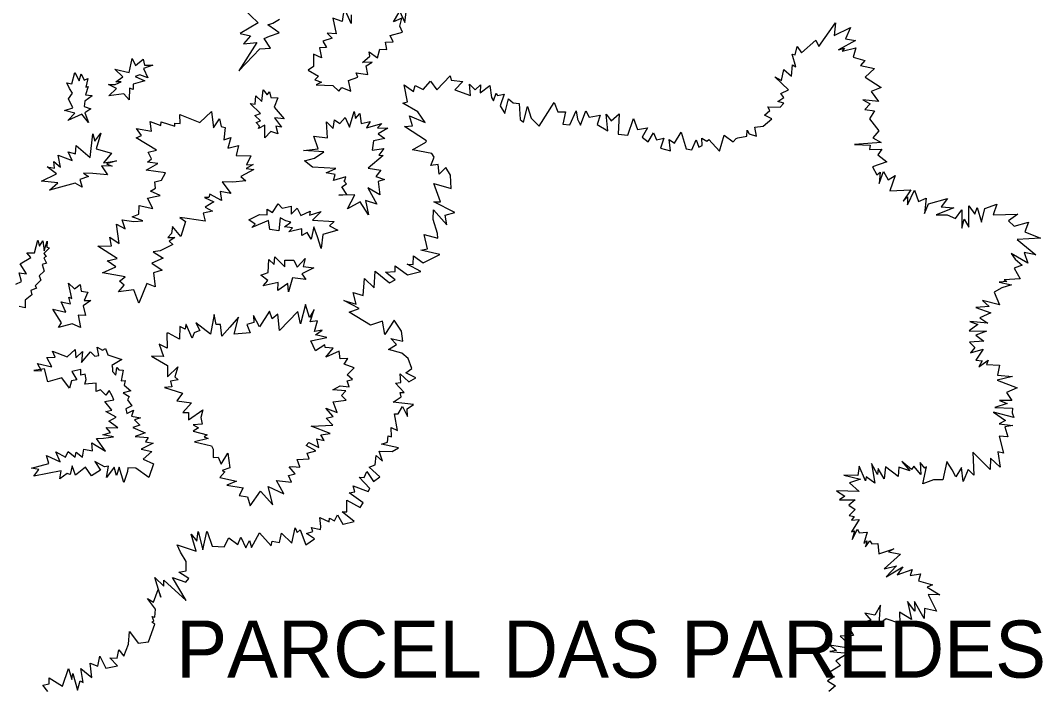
# Model space of a CAD drawing. Extents: x 662444 to 1640468, y 7452018 to 9606170.
# Drawn here: x 1134383 to 1146086, y 8020157 to 8027789 of the extents above; entities that cross this region are included whole.
import ezdxf

# ---------------------------------------------------------------- set-up
doc = ezdxf.new("R2010")
doc.units = 0
doc.layers.add('Level 1', color=7, linetype='Continuous')
doc.layers.add('Level 3', color=7, linetype='Continuous')

msp = doc.modelspace()

# ---------------------------------------------------------------- linework, layer by layer
at = {"layer": 'Level 1'}
for points in [[(1136928, 8027930), (1137105, 8027763), (1136898, 8027639), (1137018, 8027612), (1136938, 8027522), (1137089, 8027536), (1136882, 8027212), (1137125, 8027463), (1137246, 8027469), (1137173, 8027581), (1137235, 8027610), (1137346, 8027647), (1137304, 8027677), (1137217, 8027738), (1137271, 8027757), (1137349, 8027804)], [(1138170, 8027851), (1138169, 8027754), (1138090, 8027932), (1138065, 8027777), (1137958, 8027816), (1137996, 8027634), (1137896, 8027643), (1137951, 8027587), (1137845, 8027550), (1137886, 8027477), (1137805, 8027476), (1137831, 8027361), (1137740, 8027402), (1137738, 8027259), (1137676, 8027218), (1137796, 8027150), (1137753, 8027108), (1137829, 8027080), (1137768, 8027052), (1137959, 8027045), (1138029, 8026979), (1138061, 8027021), (1138167, 8026978), (1138138, 8027101), (1138246, 8027139), (1138225, 8027187), (1138360, 8027170), (1138340, 8027268), (1138410, 8027311), (1138298, 8027307), (1138383, 8027381), (1138376, 8027428), (1138471, 8027360), (1138497, 8027458), (1138579, 8027457), (1138561, 8027539), (1138651, 8027544), (1138617, 8027617), (1138757, 8027653), (1138726, 8027723), (1138749, 8027814), (1138653, 8027772), (1138715, 8027874)], [(1138724, 8027897), (1138784, 8027764), (1138804, 8027913)], [(1141809, 8026425), (1141872, 8026382), (1141947, 8026508), (1142007, 8026319), (1142071, 8026307), (1142118, 8026420), (1142152, 8026335), (1142187, 8026354), (1142186, 8026439), (1142243, 8026406), (1142264, 8026426), (1142388, 8026291), (1142440, 8026474), (1142543, 8026396), (1142577, 8026436), (1142598, 8026445), (1142700, 8026463), (1142703, 8026532), (1142727, 8026490), (1142810, 8026462), (1142793, 8026567), (1142886, 8026576), (1142986, 8026661), (1142903, 8026704), (1142962, 8026756), (1142942, 8026800), (1143080, 8026796), (1143125, 8026840), (1143054, 8026858), (1143124, 8026907), (1143090, 8026951), (1143176, 8026994), (1143020, 8027143), (1143097, 8027101), (1143125, 8027228), (1143212, 8027149), (1143222, 8027279), (1143261, 8027257), (1143220, 8027404), (1143253, 8027395), (1143276, 8027489), (1143325, 8027419), (1143492, 8027561), (1143524, 8027489), (1143716, 8027761), (1143701, 8027616), (1143886, 8027708), (1143830, 8027578), (1143945, 8027560), (1143748, 8027451), (1143818, 8027470), (1143790, 8027437), (1143950, 8027475), (1143917, 8027366), (1144050, 8027331), (1144002, 8027274), (1144162, 8027238), (1144054, 8027139), (1144237, 8027021), (1144122, 8026976), (1144206, 8026861), (1144027, 8026878), (1144112, 8026834), (1144051, 8026767), (1144161, 8026753), (1144105, 8026663), (1144213, 8026523), (1144141, 8026444), (1144239, 8026390), (1143931, 8026367), (1144113, 8026361), (1144104, 8026310), (1144247, 8026313), (1144199, 8026250), (1144304, 8026168), (1144140, 8026112), (1144188, 8026021), (1144228, 8026050), (1144214, 8025920), (1144264, 8026057), (1144318, 8025962), (1144398, 8026014), (1144336, 8025835), (1144579, 8025847), (1144489, 8025718), (1144541, 8025766), (1144539, 8025677), (1144621, 8025844), (1144664, 8025714), (1144753, 8025752), (1144733, 8025578), (1144782, 8025687), (1144996, 8025747), (1144927, 8025654), (1145069, 8025642), (1144867, 8025562), (1144995, 8025562), (1145091, 8025519), (1145161, 8025619), (1145162, 8025407), (1145188, 8025513)], [(1135899, 8027275), (1135793, 8027237), (1135841, 8027131), (1135749, 8027164), (1135697, 8027148), (1135806, 8027097), (1135672, 8027060), (1135674, 8026996), (1135632, 8027012), (1135628, 8026878), (1135568, 8026948), (1135396, 8026923), (1135483, 8027010), (1135390, 8027053), (1135469, 8027056), (1135534, 8027084), (1135476, 8027086), (1135554, 8027142), (1135464, 8027232), (1135627, 8027194), (1135663, 8027351), (1135701, 8027271), (1135786, 8027345), (1135804, 8027276), (1135899, 8027275)], [(1135163, 8026619), (1135084, 8026716), (1134924, 8026642), (1135006, 8026726), (1134886, 8026758), (1134982, 8026788), (1134934, 8026890), (1134977, 8026957), (1134946, 8027008), (1134915, 8027072), (1134971, 8027062), (1135006, 8027191), (1135054, 8027097), (1135077, 8027176), (1135113, 8027105), (1135154, 8027125), (1135131, 8027026), (1135159, 8027030), (1135128, 8026937), (1135197, 8026929), (1135204, 8026924), (1135118, 8026865), (1135111, 8026804), (1135189, 8026774), (1135119, 8026730), (1135163, 8026619)], [(1138587, 8022959), (1138594, 8023028), (1138632, 8023017), (1138628, 8023125), (1138701, 8023091), (1138666, 8023281), (1138707, 8023282), (1138757, 8023365), (1138814, 8023251), (1138811, 8023338), (1138882, 8023387), (1138651, 8023414), (1138742, 8023476), (1138731, 8023527), (1138777, 8023526), (1138678, 8023634), (1138737, 8023642), (1138732, 8023739), (1138830, 8023647), (1138910, 8023695), (1138797, 8023752), (1138866, 8023803), (1138822, 8023917), (1138748, 8023978), (1138598, 8024017), (1138690, 8024075), (1138623, 8024144), (1138763, 8024114), (1138746, 8024229), (1138661, 8024355), (1138555, 8024192), (1138527, 8024342), (1138390, 8024297), (1138146, 8024445), (1138261, 8024490), (1138085, 8024581), (1138228, 8024537), (1138194, 8024672), (1138308, 8024639), (1138323, 8024831), (1138432, 8024725), (1138445, 8024918), (1138610, 8024783), (1138673, 8024816), (1138561, 8024905), (1138673, 8024911), (1138675, 8024978), (1138816, 8024876), (1138967, 8024913), (1138809, 8024997), (1138878, 8024991), (1138882, 8025093), (1138994, 8025013), (1139184, 8025107), (1138968, 8025157), (1139043, 8025173), (1139004, 8025335), (1139162, 8025295), (1139158, 8025348), (1139107, 8025508), (1139114, 8025620), (1139266, 8025447), (1139244, 8025558), (1139358, 8025590), (1139117, 8025712), (1139193, 8025710), (1139115, 8025919), (1139313, 8025862), (1139308, 8026017), (1139252, 8026104), (1139178, 8026029), (1139164, 8026140), (1139081, 8026127), (1139120, 8026223), (1139093, 8026265), (1138871, 8026305), (1139026, 8026395), (1139032, 8026410), (1138781, 8026574), (1138871, 8026581), (1138836, 8026695), (1139015, 8026618), (1138932, 8026740), (1138762, 8026841), (1138813, 8026857), (1138778, 8027049), (1138883, 8026975), (1138904, 8027043), (1138994, 8026999), (1139077, 8027093), (1139151, 8026994), (1139304, 8027155), (1139313, 8027106), (1139450, 8027089), (1139357, 8026993), (1139537, 8026928), (1139524, 8027059), (1139588, 8026995), (1139651, 8027052), (1139648, 8026958), (1139759, 8027045)], [(1137180, 8026444), (1137181, 8026590), (1137107, 8026549), (1137120, 8026578), (1137080, 8026619), (1137130, 8026637), (1137066, 8026700), (1137130, 8026722), (1137013, 8026838), (1137070, 8026831), (1137077, 8026926), (1137147, 8026859), (1137161, 8026992), (1137208, 8026936), (1137235, 8026969), (1137251, 8026905), (1137328, 8026902), (1137286, 8026796), (1137401, 8026662), (1137290, 8026673), (1137372, 8026564), (1137305, 8026576), (1137329, 8026488), (1137248, 8026516), (1137180, 8026444)], [(1139759, 8027045), (1139777, 8026905), (1139799, 8026866), (1139829, 8026954), (1139845, 8026930), (1139922, 8026943), (1139876, 8026812), (1139928, 8026724), (1139971, 8026891), (1140023, 8026846), (1140092, 8026836), (1140106, 8026654), (1140144, 8026625), (1140188, 8026802), (1140230, 8026668), (1140321, 8026576), (1140494, 8026848), (1140537, 8026742), (1140624, 8026742), (1140594, 8026600), (1140675, 8026592), (1140744, 8026753), (1140762, 8026656), (1140795, 8026590), (1140855, 8026752), (1140893, 8026682), (1141020, 8026703), (1140987, 8026598), (1141109, 8026522), (1141091, 8026714), (1141145, 8026640), (1141238, 8026720), (1141227, 8026485), (1141339, 8026474), (1141404, 8026665), (1141449, 8026541), (1141562, 8026558), (1141500, 8026451), (1141569, 8026397), (1141632, 8026502), (1141665, 8026420), (1141748, 8026439), (1141713, 8026324), (1141825, 8026295), (1141809, 8026425)], [(1135737, 8024551), (1135680, 8024703), (1135505, 8024679), (1135570, 8024756), (1135515, 8024803), (1135582, 8024850), (1135324, 8024899), (1135474, 8024966), (1135374, 8025036), (1135492, 8025060), (1135269, 8025203), (1135425, 8025205), (1135408, 8025307), (1135513, 8025233), (1135482, 8025454), (1135580, 8025402), (1135548, 8025505), (1135680, 8025485), (1135783, 8025492), (1135661, 8025537), (1135738, 8025568), (1135742, 8025667), (1135897, 8025634), (1135839, 8025752), (1135925, 8025771), (1135984, 8025783), (1135870, 8025832), (1135928, 8025866), (1135920, 8025938), (1135999, 8025960), (1136044, 8026043), (1135822, 8026072), (1135957, 8026151), (1135837, 8026166), (1135884, 8026202), (1135846, 8026280), (1135939, 8026302), (1135706, 8026442), (1135768, 8026471), (1135711, 8026552), (1135882, 8026521), (1135867, 8026630), (1135992, 8026584), (1135995, 8026626), (1136150, 8026577), (1136151, 8026611), (1136213, 8026609), (1136208, 8026710), (1136435, 8026621), (1136572, 8026747), (1136595, 8026560), (1136662, 8026662), (1136680, 8026572), (1136727, 8026563), (1136713, 8026421), (1136793, 8026446), (1136756, 8026327), (1136880, 8026357), (1136854, 8026242), (1137020, 8026237), (1136970, 8026134), (1137046, 8026139), (1136966, 8026093), (1137055, 8026080), (1136907, 8026000), (1136962, 8025950), (1136815, 8025937), (1136693, 8025941), (1136791, 8025805), (1136671, 8025830), (1136684, 8025727), (1136553, 8025800), (1136541, 8025759), (1136490, 8025761), (1136596, 8025712), (1136499, 8025650), (1136582, 8025602), (1136473, 8025580), (1136496, 8025490), (1136290, 8025519), (1136206, 8025532), (1136271, 8025486), (1136219, 8025312), (1136123, 8025428), (1136113, 8025347), (1136071, 8025301), (1136150, 8025301), (1136087, 8025260), (1136129, 8025221), (1135981, 8025149), (1135902, 8025139), (1136017, 8025066), (1135887, 8025008), (1136005, 8024929), (1135907, 8024898), (1135925, 8024737), (1135828, 8024775), (1135737, 8024551)], [(1138369, 8025560), (1138271, 8025709), (1138128, 8025629), (1138210, 8025792), (1138029, 8025786), (1138121, 8025795), (1138063, 8025882), (1138117, 8025916), (1138085, 8025952), (1138098, 8025957), (1138107, 8025995), (1137968, 8025956), (1137987, 8026022), (1137885, 8026041), (1137993, 8026091), (1137727, 8026107), (1137637, 8026181), (1137750, 8026209), (1137855, 8026282), (1137625, 8026300), (1137792, 8026317), (1137741, 8026464), (1137898, 8026444), (1137887, 8026628), (1137964, 8026549), (1137978, 8026651), (1138040, 8026608), (1138099, 8026678), (1138149, 8026567), (1138203, 8026746), (1138218, 8026667), (1138269, 8026723), (1138283, 8026606), (1138388, 8026630), (1138345, 8026557), (1138521, 8026608), (1138470, 8026558), (1138588, 8026555), (1138479, 8026489), (1138556, 8026435), (1138427, 8026410), (1138411, 8026304), (1138543, 8026321), (1138486, 8026246), (1138537, 8026243), (1138366, 8026097), (1138511, 8026072), (1138452, 8025999), (1138551, 8025968), (1138479, 8025945), (1138497, 8025789), (1138359, 8025872), (1138462, 8025682), (1138334, 8025727), (1138369, 8025560)], [(1134623, 8025949), (1134794, 8026032), (1134689, 8026110), (1134774, 8026097), (1134765, 8026171), (1134840, 8026107), (1134813, 8026244), (1134974, 8026183), (1134930, 8026284), (1135014, 8026261), (1135020, 8026355), (1135181, 8026217), (1135210, 8026489), (1135233, 8026407), (1135303, 8026496), (1135251, 8026317), (1135426, 8026268), (1135333, 8026156), (1135482, 8026181), (1135369, 8026145), (1135434, 8026120), (1135312, 8026123), (1135380, 8026019), (1135212, 8026034), (1135104, 8026038), (1135160, 8026000), (1135064, 8025966), (1135091, 8025877), (1135011, 8025924), (1134840, 8025878), (1134716, 8025843), (1134809, 8025927), (1134623, 8025949)], [(1137845, 8025337), (1137827, 8025176), (1137785, 8025310), (1137743, 8025425), (1137711, 8025284), (1137666, 8025360), (1137604, 8025324), (1137604, 8025400), (1137457, 8025365), (1137496, 8025412), (1137407, 8025424), (1137478, 8025479), (1137422, 8025491), (1137357, 8025526), (1137340, 8025379), (1137240, 8025392), (1137223, 8025497), (1137032, 8025416), (1137071, 8025456), (1136996, 8025504), (1137118, 8025565), (1137207, 8025562), (1137209, 8025628), (1137268, 8025588), (1137335, 8025688), (1137379, 8025638), (1137482, 8025662), (1137481, 8025571), (1137553, 8025638), (1137594, 8025554), (1137700, 8025604), (1137691, 8025559), (1137825, 8025600), (1137727, 8025501), (1137973, 8025486), (1137920, 8025434), (1138016, 8025387), (1137845, 8025337)], [(1145188, 8025513), (1145241, 8025420), (1145242, 8025664), (1145310, 8025568), (1145338, 8025646), (1145387, 8025476), (1145425, 8025636), (1145562, 8025685), (1145520, 8025563), (1145805, 8025569), (1145697, 8025494), (1145761, 8025433), (1145926, 8025476), (1145882, 8025368), (1146061, 8025293), (1145794, 8025278), (1146011, 8025103), (1145875, 8025130), (1145917, 8025009), (1145728, 8025117), (1145774, 8025052), (1145854, 8024986), (1145763, 8024952), (1145831, 8024830), (1145647, 8024818), (1145676, 8024799), (1145590, 8024790), (1145729, 8024759), (1145621, 8024724), (1145532, 8024676), (1145594, 8024531), (1145398, 8024579), (1145475, 8024510), (1145321, 8024499), (1145493, 8024440), (1145369, 8024383), (1145459, 8024319), (1145252, 8024340), (1145346, 8024307), (1145246, 8024233), (1145446, 8024229), (1145322, 8024182), (1145414, 8024115), (1145250, 8024103), (1145310, 8024042), (1145261, 8023982), (1145406, 8024021), (1145322, 8023896), (1145396, 8023888), (1145358, 8023820), (1145463, 8023897), (1145446, 8023846), (1145594, 8023841), (1145572, 8023726), (1145743, 8023709), (1145566, 8023668), (1145795, 8023579), (1145673, 8023526), (1145734, 8023435), (1145594, 8023434), (1145680, 8023401), (1145540, 8023355), (1145742, 8023348), (1145740, 8023292), (1145756, 8023240), (1145523, 8023302), (1145663, 8023205), (1145590, 8023166), (1145745, 8023149), (1145653, 8023134), (1145688, 8023017), (1145588, 8023026), (1145640, 8022830), (1145574, 8022847), (1145600, 8022671), (1145490, 8022773), (1145486, 8022646), (1145288, 8022841), (1145299, 8022578), (1145235, 8022646), (1145176, 8022508), (1145159, 8022667), (1145092, 8022562), (1145051, 8022642), (1144992, 8022736), (1144945, 8022525), (1144837, 8022524), (1144715, 8022481), (1144758, 8022673), (1144739, 8022658), (1144685, 8022726), (1144691, 8022588), (1144612, 8022682), (1144585, 8022643), (1144473, 8022735), (1144566, 8022630), (1144440, 8022670), (1144431, 8022563), (1144286, 8022675), (1144272, 8022537), (1144204, 8022655)], [(1134331, 8024768), (1134396, 8024799), (1134369, 8024899), (1134452, 8024886), (1134379, 8025001), (1134502, 8025071), (1134456, 8025128), (1134545, 8025128), (1134580, 8025272), (1134599, 8025203), (1134639, 8025265), (1134653, 8025150)], [(1134653, 8025150), (1134687, 8025259), (1134683, 8025190), (1134714, 8025185), (1134652, 8025118), (1134676, 8025086), (1134650, 8025069), (1134682, 8025009), (1134633, 8024993), (1134656, 8024917), (1134598, 8024864), (1134616, 8024814), (1134550, 8024749), (1134568, 8024721), (1134501, 8024693), (1134514, 8024644), (1134435, 8024585), (1134435, 8024498), (1134369, 8024513)], [(1137642, 8025060), (1137621, 8024970), (1137743, 8024956), (1137605, 8024884), (1137649, 8024819), (1137499, 8024840), (1137451, 8024680), (1137443, 8024775), (1137331, 8024694), (1137334, 8024788), (1137161, 8024750), (1137214, 8024808), (1137134, 8024871), (1137220, 8024900), (1137225, 8025048), (1137287, 8024994), (1137294, 8025081), (1137409, 8024967), (1137411, 8025042), (1137513, 8025041), (1137551, 8024963), (1137642, 8025060)], [(1134752, 8024480), (1134902, 8024448), (1134849, 8024566), (1134956, 8024543), (1134938, 8024618), (1134971, 8024604), (1134933, 8024778), (1135000, 8024715), (1135068, 8024762), (1135076, 8024687), (1135155, 8024677), (1135111, 8024581), (1135188, 8024579), (1135102, 8024518), (1135126, 8024410), (1135042, 8024412), (1135070, 8024271), (1134974, 8024312), (1134820, 8024269), (1134854, 8024326), (1134752, 8024480)], [(1136308, 8023296), (1136306, 8023214), (1136472, 8023326), (1136447, 8023240), (1136462, 8023163), (1136362, 8023154), (1136422, 8023121), (1136360, 8023082), (1136520, 8023043), (1136488, 8023019), (1136531, 8023000), (1136374, 8022961), (1136569, 8022915), (1136591, 8022877), (1136588, 8022781), (1136647, 8022784), (1136681, 8022707), (1136758, 8022832), (1136781, 8022662), (1136693, 8022632), (1136724, 8022618), (1136665, 8022554), (1136855, 8022512), (1136744, 8022464), (1136933, 8022433), (1136886, 8022347), (1136983, 8022331), (1137013, 8022228), (1137133, 8022395), (1137272, 8022238), (1137219, 8022449), (1137399, 8022364), (1137316, 8022517), (1137487, 8022499), (1137451, 8022574), (1137528, 8022595), (1137460, 8022676), (1137498, 8022677), (1137580, 8022670), (1137580, 8022674), (1137552, 8022760), (1137687, 8022765), (1137667, 8022833), (1137765, 8022858), (1137654, 8022918), (1137686, 8022955), (1137799, 8022895), (1137777, 8022995), (1137861, 8022978), (1137824, 8023043), (1137930, 8023055), (1137710, 8023141), (1137959, 8023153), (1137882, 8023232), (1137962, 8023253), (1137881, 8023348), (1138009, 8023297), (1137962, 8023419), (1138114, 8023437), (1138059, 8023490), (1138107, 8023547), (1137961, 8023557), (1138045, 8023601), (1138145, 8023590), (1138123, 8023661), (1138186, 8023677), (1138124, 8023730), (1138205, 8023810), (1138089, 8023849), (1138130, 8023917), (1138045, 8023912), (1138032, 8024001), (1137879, 8023930), (1137962, 8024035), (1137872, 8024040), (1137868, 8024071), (1137763, 8024002), (1137709, 8024120), (1137889, 8024157), (1137760, 8024185), (1137838, 8024240), (1137750, 8024225), (1137785, 8024348), (1137701, 8024337), (1137744, 8024476), (1137692, 8024386), (1137647, 8024533), (1137589, 8024313), (1137558, 8024454), (1137349, 8024238), (1137331, 8024423), (1137264, 8024369), (1137233, 8024457), (1137118, 8024279), (1137053, 8024407), (1137056, 8024328), (1136973, 8024305), (1137013, 8024211), (1136831, 8024194), (1136881, 8024391), (1136780, 8024274)], [(1136780, 8024274), (1136689, 8024170), (1136673, 8024307), (1136624, 8024305), (1136602, 8024421), (1136557, 8024195), (1136392, 8024323), (1136435, 8024235), (1136371, 8024208), (1136348, 8024150), (1136282, 8024304), (1136277, 8024304), (1136270, 8024251), (1136207, 8024283), (1136202, 8024137), (1136076, 8024206), (1136058, 8024206), (1136063, 8024035), (1135970, 8024081), (1136019, 8023939), (1135884, 8023944), (1136067, 8023835), (1136068, 8023705), (1136184, 8023822), (1136150, 8023705), (1136189, 8023670), (1136102, 8023655), (1136117, 8023593), (1136033, 8023583), (1136239, 8023517), (1136172, 8023430), (1136340, 8023407), (1136241, 8023296), (1136308, 8023296)], [(1135608, 8022623), (1135565, 8022496), (1135514, 8022669), (1135482, 8022574), (1135454, 8022669), (1135368, 8022552), (1135390, 8022683), (1135344, 8022675), (1135233, 8022737), (1135299, 8022636), (1135197, 8022571), (1135129, 8022672), (1135013, 8022581), (1134976, 8022687), (1134952, 8022585), (1134919, 8022600), (1134832, 8022538), (1134848, 8022630), (1134534, 8022566), (1134593, 8022646), (1134511, 8022658), (1134708, 8022713), (1134682, 8022804), (1134837, 8022732), (1134789, 8022848), (1134899, 8022787), (1134930, 8022849), (1135010, 8022786), (1135021, 8022841), (1135094, 8022787), (1135108, 8022877), (1135206, 8022858), (1135199, 8022948), (1135357, 8022854), (1135254, 8023000), (1135333, 8023002), (1135449, 8023020), (1135325, 8023042), (1135412, 8023069), (1135366, 8023125), (1135499, 8023123), (1135483, 8023133), (1135396, 8023199), (1135480, 8023243), (1135361, 8023308), (1135429, 8023322), (1135348, 8023423), (1135451, 8023444), (1135431, 8023488), (1135400, 8023548), (1135360, 8023495), (1135298, 8023555), (1135251, 8023539), (1135249, 8023634), (1135121, 8023623), (1135135, 8023674), (1135124, 8023738), (1135073, 8023726), (1135075, 8023788), (1134970, 8023768), (1135028, 8023672), (1134968, 8023658), (1134946, 8023574), (1134857, 8023693), (1134697, 8023649), (1134659, 8023798), (1134535, 8023777), (1134622, 8023774), (1134576, 8023860), (1134743, 8023821), (1134685, 8023927), (1134780, 8023930), (1134751, 8024000), (1134919, 8023933), (1135011, 8024017), (1135017, 8023922), (1135092, 8023997), (1135081, 8023871), (1135184, 8023992), (1135233, 8023943), (1135279, 8023952), (1135262, 8024045), (1135323, 8024013), (1135357, 8024032), (1135385, 8023956), (1135542, 8023906), (1135429, 8023835), (1135437, 8023809), (1135436, 8023766), (1135475, 8023726), (1135485, 8023813), (1135510, 8023787), (1135559, 8023783), (1135534, 8023658), (1135583, 8023664), (1135571, 8023611), (1135645, 8023544), (1135560, 8023521), (1135628, 8023479), (1135608, 8023441), (1135657, 8023374)], [(1135657, 8023374), (1135588, 8023339), (1135601, 8023287), (1135677, 8023324), (1135654, 8023256), (1135759, 8023235), (1135689, 8023213), (1135748, 8023153), (1135671, 8023127), (1135810, 8023066), (1135697, 8023022), (1135846, 8023011), (1135814, 8022961), (1135903, 8022944), (1135765, 8022878), (1135887, 8022850), (1135789, 8022761), (1135908, 8022710), (1135852, 8022552), (1135702, 8022659), (1135614, 8022662), (1135608, 8022623)], [(1135100, 8020204), (1135075, 8020366), (1135200, 8020262), (1135181, 8020426), (1135270, 8020391), (1135292, 8020505), (1135362, 8020367), (1135493, 8020394), (1135408, 8020486), (1135490, 8020483), (1135511, 8020577), (1135565, 8020504), (1135621, 8020645), (1135631, 8020790), (1135729, 8020655), (1135847, 8020671), (1135920, 8020871), (1135887, 8020894), (1135909, 8020911), (1135892, 8020961), (1135923, 8020954), (1135930, 8021046), (1135837, 8021167), (1135905, 8021126), (1135959, 8021268), (1135991, 8021180), (1135921, 8021405), (1136024, 8021307), (1136026, 8021376), (1136280, 8021143), (1136124, 8021406), (1136276, 8021355), (1136310, 8021395), (1136197, 8021469), (1136280, 8021482), (1136281, 8021590), (1136215, 8021697), (1136177, 8021783), (1136395, 8021707), (1136339, 8021902), (1136404, 8021825), (1136417, 8021933), (1136472, 8021724), (1136517, 8021932), (1136522, 8021932), (1136578, 8021764), (1136714, 8021758), (1136768, 8021860), (1136870, 8021785), (1136906, 8021868), (1136964, 8021746), (1137007, 8021832), (1137028, 8021750), (1137121, 8021920), (1137254, 8021768), (1137266, 8021823), (1137350, 8021806), (1137373, 8021914), (1137492, 8021802), (1137527, 8021976), (1137553, 8021924), (1137585, 8021954), (1137651, 8021783), (1137751, 8021851), (1137658, 8021911), (1137732, 8021934), (1137717, 8021980), (1137820, 8021957), (1137824, 8021992), (1137810, 8022093), (1137918, 8022046), (1137921, 8022086), (1137979, 8022056), (1138012, 8022126), (1138073, 8022018), (1138078, 8022018), (1138202, 8022049), (1138068, 8022158), (1138121, 8022160), (1138118, 8022294), (1138271, 8022208), (1138306, 8022263), (1138146, 8022378), (1138213, 8022389), (1138192, 8022456), (1138366, 8022394), (1138383, 8022427), (1138260, 8022558), (1138318, 8022554), (1138348, 8022622), (1138426, 8022505), (1138497, 8022561), (1138375, 8022672), (1138443, 8022696), (1138454, 8022803), (1138529, 8022738), (1138489, 8022855), (1138638, 8022851), (1138713, 8022894), (1138515, 8022934), (1138587, 8022959)], [(1144204, 8022655), (1144197, 8022588), (1144127, 8022711), (1144167, 8022489), (1144065, 8022562), (1144059, 8022514), (1143985, 8022684), (1143971, 8022576), (1143812, 8022581), (1144001, 8022534), (1143877, 8022491), (1143985, 8022393), (1143725, 8022401), (1143823, 8022340), (1143763, 8022295), (1143940, 8022297), (1143868, 8022236), (1143940, 8022185), (1143870, 8022118), (1143928, 8022106), (1143898, 8022064), (1143986, 8022073), (1143897, 8021931), (1143932, 8021943), (1143907, 8021841), (1143969, 8021959), (1143988, 8021918), (1144076, 8021925), (1144041, 8021796), (1144075, 8021826), (1144060, 8021757), (1144108, 8021827), (1144130, 8021793), (1144201, 8021796), (1144210, 8021678), (1144384, 8021737), (1144324, 8021700), (1144459, 8021675), (1144272, 8021505), (1144414, 8021541), (1144295, 8021415), (1144485, 8021529), (1144420, 8021436), (1144594, 8021497), (1144571, 8021429), (1144687, 8021448), (1144664, 8021367), (1144826, 8021321), (1144764, 8021297), (1144911, 8021208), (1144776, 8021212), (1144870, 8021020), (1144735, 8021052), (1144731, 8020938), (1144620, 8021133), (1144622, 8021020), (1144541, 8021133), (1144586, 8020927), (1144448, 8021011), (1144451, 8020880), (1144294, 8020934), (1144217, 8020875), (1144232, 8021090), (1144167, 8020976), (1144053, 8020999), (1144120, 8020920), (1144018, 8020887), (1143873, 8020825), (1143921, 8020742), (1143770, 8020734), (1143934, 8020585), (1143652, 8020630), (1143727, 8020570), (1143650, 8020561), (1143861, 8020540), (1143720, 8020452), (1143772, 8020399), (1143605, 8020295), (1143704, 8020271), (1143623, 8020225), (1143714, 8020166), (1143639, 8020100)], [(1134698, 8020100), (1134638, 8020173), (1134713, 8020187), (1134710, 8020256), (1134866, 8020161), (1134934, 8020365), (1134971, 8020239), (1134981, 8020308), (1135036, 8020117), (1135067, 8020223), (1135100, 8020204)]]:
    msp.add_lwpolyline(points, dxfattribs=at)

# ---------------------------------------------------------------- texts
at = {"layer": 'Level 3'}
msp.add_text('PARCEL DAS PAREDES', height=653.79, dxfattribs=at).set_placement((1136166, 8020260))

doc.saveas('drawing.dxf')
